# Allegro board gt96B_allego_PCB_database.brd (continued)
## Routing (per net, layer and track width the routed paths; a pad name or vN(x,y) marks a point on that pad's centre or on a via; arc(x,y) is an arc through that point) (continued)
SDCARD_CMD_CONN: length 19.1
  TOP w0.201: J5.3 8.34,1.75 9.04,2.45 v1(9.28,2.45)
  L3 w0.151: v1(10.15,16.83) 11.22,15.76 11.22,15.73 11.38,15.57 11.38,2.93 10.9,2.45 v1(9.28,2.45)
  L5 w0.084: v4(9.25,17.03) 9.95,17.03 v1(10.15,16.83)
SDCARD_D0: length 38.1
  L5 w0.084: v1(9.26,22.05) 9.9,22.05 10.45,21.49 15.39,21.49 18.68,18.2 33.52,18.2 35.75,20.43 37.65,20.43 38.88,21.66 v1(38.88,22.51)
  BOTTOM w0.201: v1(9.26,22.05) 9.2,22 9.2,21.41 9.25,21.36 U1.D1 ; J2.81 v1(38.88,22.51)
SDCARD_D0_CONN: length 19.6
  TOP w0.201: v1(4.24,2.45) 3.75,2.45 3.68,2.38 3.68,1.81 J5.7
  L3 w0.151: v1(9.37,15.79) 9.2,15.62 9.2,14.97 9.26,14.91 9.26,14.56 9.2,14.5 9.2,7.71 5.11,3.62 3.59,3.62 3.49,3.52 3.49,3.38 3.75,3.12 4.11,3.12 4.24,2.99 v1(4.24,2.45)
  BOTTOM w0.201: v1(9.37,15.79) 9.37,16.42 9.25,16.54 U1.D5
SDCARD_D1: length 37.5
  L5 w0.084: v1(39.28,22.06) 39.28,21.78 37.73,20.23 35.83,20.23 33.6,18 18.6,18 15.31,21.29 9.96,21.29 v1(9.65,21.6)
  BOTTOM w0.1: J2.83 v1(39.28,22.06)
  BOTTOM w0.201: U1.E1 v1(9.65,21.6)
SDCARD_D1_CONN: length 20.2
  TOP w0.201: J5.8 2.84,2.15 v1(2.54,2.45)
  L3 w0.151: v1(2.54,2.45) 2.97,2.02 4.51,2.02 4.75,2.26 4.75,2.73 9.51,7.49 9.51,15.17 v1(9.95,15.61)
  BOTTOM w0.201: U1.E5 9.82,16.46 9.82,15.72 9.96,15.58 9.96,15.61 v1(9.95,15.61)
SDCARD_D2: length 38.2
  L5 w0.084: v1(8.05,19.95) 9.13,19.95 10.27,21.09 15.22,21.09 18.51,17.8 33.68,17.8 35.91,20.03 37.82,20.03 39.68,21.89 v1(39.68,22.51)
  BOTTOM w0.201: J2.85 v1(39.68,22.51) ; v1(8.05,19.95) 8.05,19.74 8,19.69 8,19.31 8.05,19.26 U1.A1
SDCARD_D2_CONN: length 18.9
  TOP w0.201: v1(10.9,3.2) 10.54,2.84 J5.1
  L3 w0.151: v1(10.9,3.2) 11.09,3.39 11.09,15.5 10.96,15.63 10.96,15.65 10.26,16.35 9.86,16.35 9.62,16.59 8.11,16.59 7.9,16.38 7.9,16.12 v1(7.85,16.07)
  BOTTOM w0.201: U1.A5 7.85,16.43 v1(7.85,16.07)
SDCARD_D3: length 37.9
  L5 w0.084: v1(8.45,19.5) 9.04,19.5 10.43,20.89 15.14,20.89 18.43,17.6 33.77,17.6 36,19.83 37.92,19.83 40.08,21.99 v1(40.08,22.06)
  BOTTOM w0.1: J2.87 v1(40.08,22.06)
  BOTTOM w0.201: U1.B1 v1(8.45,19.5)
SDCARD_D3_CONN: length 20
  TOP w0.201: v1(7.81,3.2) 9.18,3.2 9.78,2.6 9.78,2.09 9.44,1.75 J5.2
  L3 w0.151: v1(8.45,16.16) 8.51,16.22 9.55,16.22 9.72,16.05 10.12,16.05 10.81,15.36 10.81,6.2 v1(7.81,3.2)
  BOTTOM w0.201: v1(8.45,16.16) 8.45,16.16 U1.B5
SDCARD_LVL_CLK_FB: length 37.3
  L5 w0.084: v1(38.08,22.51) 38.08,21.43 37.48,20.83 35.58,20.83 33.35,18.6 18.84,18.6 14.54,22.91 11.41,22.91 10.57,22.06 v1(10.45,22.06)
  BOTTOM w0.15: 9.77,17.9 9.94,18.07
  BOTTOM w0.201: 9.94,18.07 9.98,18.11 9.98,21.01 10.45,21.48 v1(10.45,22.06) ; J2.77 v1(38.08,22.51) ; U1.E2 9.73,17.9 9.77,17.9
SDCARD_LVL_CMD_DIR: length 45.3
  L5 w0.084: v1(40.58,25.25) 40.58,23.36 40.33,23.11 35.03,23.11 34.68,22.76 34.68,21.35 33.98,20.64 32.56,20.64 31.41,19.5 28.94,19.5 28.64,19.8 18.49,19.8 14.79,23.5 8.9,23.5 v1(7.81,22.41)
  BOTTOM w0.1: 7.54,18.28 7.45,18.38 7.45,18.62 7.5,18.67
  BOTTOM w0.201: 7.5,18.67 7.63,18.8 7.63,19.73 7.6,19.76 7.6,20.13 7.63,20.16 7.63,22.23 v1(7.81,22.41) ; v1(40.58,25.25) 40.48,25.35 J2.90 ; U1.A2 7.99,17.83 7.54,18.28
SDCARD_LVL_DAT_DIR: length 40.8
  L3 w0.151: v1(7.12,17.92) 7.16,17.96 10.53,17.96 v1(10.58,17.91)
  L5 w0.084: v1(10.55,22.89) 10.96,23.3 14.71,23.3 18.41,19.6 28.55,19.6 28.85,19.3 31.48,19.3 32.62,20.44 34.63,20.44 36.08,21.89 v1(36.08,22.51)
  BOTTOM w0.1: 7.97,17.43 7.96,17.43 7.64,17.75 ; J2.67 v1(36.08,22.51) ; U1.E3 10.05,17.83 10.13,17.83 10.18,17.88
  BOTTOM w0.201: v1(7.12,17.92) 7.29,17.75 7.64,17.75 ; 10.18,17.88 10.55,17.88 v1(10.58,17.91) 10.9,18.23 10.9,18.77 10.9,18.77 10.9,19.32 10.9,19.33 10.9,19.53 10.9,19.54 10.9,20.09 10.9,20.09 10.9,20.17 10.9,20.17 10.9,20.54 10.9,20.54 10.9,22.54 v1(10.55,22.89) ; 7.97,17.43 U1.A3
SDCARD_LVL_SEL: length 45.7
  L5 w0.084: v1(7.32,22.97) 7.36,22.93 7.48,22.93 8.26,23.7 14.87,23.7 18.58,20 28.72,20 29.02,19.7 31.35,19.7 32.5,20.84 33.89,20.84 34.48,21.43 34.48,22.84 34.95,23.31 39.83,23.31 40.14,23.62 v1(40.14,24.85) ; v1(7.16,19.25) 8.45,17.96 v4(8.45,17.88)
  BOTTOM w0.1: U1.B2 v4(8.45,17.88)
  BOTTOM w0.201: v1(7.32,22.97) 7.27,22.93 7.27,20.85 7.16,20.74 v1(7.16,19.25) ; J2.88 40.08,24.91 v1(40.14,24.85)
SDCARD_PWR_DOWN_N: length 38.9
  L5 w0.084: v1(40.88,21.78) 40.76,21.66 40.03,21.66 37.99,19.62 36.07,19.62 33.85,17.4 18.35,17.4 15.06,20.69 10.78,20.69 v1(10.45,20.36) 8.85,18.76 v4(8.85,17.83)
  BOTTOM w0.1: J2.91 v1(40.88,21.78)
  BOTTOM w0.201: v1(10.45,20.36) 10.45,20.35 R36.1
SPI_0_CLK: length 32.8
  TOP w0.1: v3(18.98,40.88) 18.76,40.66 18.76,39.19 19.2,38.75 19.2,34.97 20.71,33.46 20.71,23.53 21.17,23.07 21.17,22.19 21.39,21.97 21.39,20.08 20.55,19.24 20.55,16.5 22.43,14.62 23.21,14.62 23.43,14.4 23.95,14.4 24.35,14 J13.9
  BOTTOM w0.1: J3.59 v3(18.98,40.88)
SPI_0_FS0: length 36.3
  TOP w0.1: v1(22.57,38.44) 22.58,38.45 v1(22.58,41.42) ; J13.7 23.55,13.99 23.12,14.42 22.35,14.42 20.35,16.42 20.35,19.33 21.19,20.17 21.19,21.89 20.97,22.11 20.97,22.97 20.35,23.59 20.35,33.39 18.98,34.76 18.98,38.17 v3(18.73,38.42)
  BOTTOM w0.1: v3(18.73,38.42) 19.18,37.97 22.1,37.97 v1(22.57,38.44) ; J3.77 v1(22.58,41.42)
SPI_0_MISO: length 36.1
  TOP w0.1: v1(19.16,40.17) 18.96,39.97 18.96,39.27 19.4,38.84 19.4,38.55 19.9,38.05 v2(20.32,38.05) 19.55,37.28 19.55,35.08 20.98,33.65 20.98,23.69 21.37,23.3 21.37,22.27 21.59,22.05 21.59,20 20.75,19.16 20.75,16.59 22.52,14.82 23.29,14.82 23.51,14.6 24.55,14.6 25.15,14 J13.11
  BOTTOM w0.1: v1(19.16,40.17) 18.96,39.97 18.07,39.97 16.98,41.06 J3.49
SPI_0_MOSI: length 31
  TOP w0.1: J13.1 21.15,15.34 20.15,16.34 20.15,18.92 18.28,20.79 18.28,29.91 18.98,30.62 18.98,31.04 18.99,31.05 18.99,31.65 18.98,31.66 18.98,33.93 v2(18.53,34.38) 18.62,34.47 18.62,37.55 18.23,37.94 18.23,40.27 18.36,40.4 v1(18.36,40.52)
  BOTTOM w0.1: v1(18.36,40.52) 18.36,40.57 18.44,40.65 18.44,40.99 18.58,41.13 J3.57
SPI_1_CLK: length 47.5
  TOP w0.1: v1(15.01,52.76) 15.01,52.76 15.66,52.76 16,52.42 J12.8 ; v1(33.38,21.9) 33.83,22.35 33.83,23.23 34.59,23.99 34.77,23.99 34.88,24.09 34.88,26.17 33.48,27.56 33.2,27.56 32.73,28.03 32.73,28.32 32.14,28.9 31.48,29.56 31.48,29.62 31.28,29.82 31.28,30.08 30.26,31.1 30.26,32.43 30.07,32.62 30.07,38.06 30.08,38.07 30.08,41.52 29.8,41.8 v1(29.8,41.96)
  BOTTOM w0.1: v1(29.8,41.96) 29.72,42.04 29.39,42.04 28.8,42.63 28.8,45.25 27.21,46.84 25.45,46.84 24.92,47.38 24.25,47.38 22.18,49.44 22.18,51.09 21.43,51.84 16.58,51.84 15.66,52.76 v1(15.01,52.76) ; v1(33.38,21.9) 33.38,22.66 33.28,22.76 J2.53
SPI_1_FS0: length 45.1
  TOP w0.1: v1(30.2,42.77) 30.2,41.68 30.28,41.6 30.28,37.99 30.27,37.98 30.27,32.7 30.46,32.52 30.46,31.19 31.48,30.16 31.48,29.91 31.68,29.71 31.68,29.65 32.23,29.1 32.93,28.4 32.93,28.11 33.28,27.76 33.57,27.76 35.08,26.25 35.08,23.91 34.2,23.03 34.2,21.82 v1(33.78,21.4) ; v1(19.09,52.76) 19.46,52.76 J12.12
  BOTTOM w0.1: v1(30.2,42.77) 30.2,42.74 30.02,42.56 29.43,42.56 29.2,42.79 29.2,45.42 27.38,47.24 25.62,47.24 25.08,47.78 24.42,47.78 22.59,49.61 22.59,51.37 21.71,52.24 19.99,52.24 19.47,52.76 v1(19.09,52.76) ; v1(33.78,21.4) 33.78,22.64 33.68,22.74 J2.55
SPI_1_MISO: length 44.8
  TOP w0.1: J12.10 17.48,52.74 v1(17.09,52.74) ; v1(30.81,42.55) 30.47,42.21 30.47,41.7 30.48,41.69 30.48,37.91 30.47,37.9 30.47,32.79 30.66,32.6 30.66,31.27 31.68,30.25 31.68,29.99 31.88,29.79 31.88,29.73 32.31,29.3 33.13,28.48 33.13,28.2 33.36,27.96 33.65,27.96 35.28,26.33 v1(35.28,22.51)
  BOTTOM w0.1: v1(17.09,52.74) 17.49,52.74 18.19,52.04 21.63,52.04 22.39,51.28 22.39,49.53 24.34,47.58 25,47.58 25.53,47.04 27.3,47.04 29,45.34 29,42.71 29.35,42.36 30.62,42.36 v1(30.81,42.55) ; J2.63 v1(35.28,22.51)
SPI_1_MOSI: length 43.2
  TOP w0.1: v1(21.09,52.71) 21.51,52.71 J12.14 ; v1(29.6,42.96) 29.4,42.76 29.4,41.57 29.48,41.49 29.48,40.76 29.88,40.36 29.88,38.16 29.87,38.15 29.87,32.54 30.06,32.35 30.06,31.02 31.08,30 31.08,29.74 31.28,29.54 31.28,29.48 32.06,28.7 32.53,28.23 32.53,27.95 33.12,27.36 33.4,27.36 33.89,26.88 33.89,25.21 32.88,24.21 32.88,22.6 v1(32.97,22.5)
  BOTTOM w0.1: v1(32.97,22.5) 32.88,22.6 J2.51 ; v1(21.09,52.71) 21.52,52.71 22.79,51.45 22.79,49.69 23.19,49.29 24.16,49.29 25.52,50.66 25.52,50.89 25.61,50.97 27.01,50.97 27.09,50.89 27.09,47.81 29.4,45.5 29.4,43.06 29.5,42.96 v1(29.6,42.96)
TP_HDMI_CEC: length 9.1
  TOP w0.1: J10.13 23.75,8.23 22.23,6.71 17.2,6.71 TP1.1
TP_USB_TYPC_SBU1_CONN: length 1.8
  TOP w0.1: J7.A8 42.45,10.24 42.45,11.68 TP17.1
TP_USB_TYPC_SBU2_CONN: length 10.2
  TOP w0.1: J7.B8 41.4,7.63 41.4,5.67 39.03,3.3 TP18.1
UART_0_CTS: length 9.2
  TOP w0.1: v3(16.58,41.5) 15.38,42.7 15.38,43.67 14.74,44.31 14.74,45.64 14,46.38 13.95,46.38 13.82,46.51 13.44,46.51 13.17,46.78 13,46.78 J12.3
  BOTTOM w0.1: J3.47 v3(16.58,41.5)
UART_0_RTS: length 8.1
  TOP w0.1: v1(18.18,41.31) 18.18,42.81 17.16,43.83 17.16,43.97 17.18,43.99 17.18,44.23 18,45.05 J12.9
  BOTTOM w0.1: J3.55 v1(18.18,41.31)
UART_0_RXD: length 10.2
  TOP w0.1: v1(17.8,40.8) 17.8,41.12 17.78,41.14 17.78,41.47 17.98,41.67 17.98,42.73 16.96,43.75 16.96,44.05 16.98,44.07 16.98,44.31 17.78,45.11 17.78,46.16 16.16,47.78 J12.7
  BOTTOM w0.1: J3.51 17.38,41.22 v1(17.8,40.8)
UART_0_TXD: length 48.2
  TOP w0.1: J12.5 14,47.31 14.97,46.34 15.11,46.34 v1(15.15,46.38) ; v3(31.03,41.76) 30.68,41.41 30.68,37.82 30.67,37.82 30.67,32.87 30.86,32.68 30.86,31.35 32.09,30.12 33.89,30.12 38.08,25.93 38.08,24.91 39.27,23.72 40.07,23.72 v1(41.28,22.51)
  BOTTOM w0.1: v1(41.28,22.51) J2.93 ; v1(15.15,46.38) 15.95,47.17 24.83,47.17 25.37,46.64 27.13,46.64 28.6,45.17 28.6,42.55 29.61,41.54 30.81,41.54 v3(31.03,41.76)
UART_1_RXD: length 1.5
  TOP w0.1: TP8.1 27.16,26.47 v1(27.68,26.99)
  BOTTOM w0.1: J2.26 v1(27.68,26.99)
UART_1_TXD: length 2.7
  TOP w0.1: TP9.1 28.08,26.74 v3(28.08,27.66)
  BOTTOM w0.1: v3(28.08,27.66) J2.28
UART_2_CTS: length 30.3
  TOP w0.1: v3(36.88,29.41) 37.15,29.68 37.78,29.68 38.67,30.57 38.67,35.3 37.51,36.46 37.51,40.15 36.82,40.84 36.82,41.08 35.69,42.21 35.69,45.13 34.84,45.98 33.83,45.98 33.11,46.7 33.11,49.06 33.05,49.12 v1(33.05,49.59)
  BOTTOM w0.1: J9.6 33.93,50.98 33.05,50.1 v1(33.05,49.59) ; J2.74 37.28,29.01 v3(36.88,29.41)
UART_2_RTS: length 40
  TOP w0.1: v1(37.75,28.45) 37.75,29.27 37.97,29.49 37.97,29.58 38.87,30.48 38.87,35.39 38.31,35.95 38.31,37.42 38.1,37.63 38.1,38.29 37.91,38.48 37.91,40.31 37.22,41 37.22,41.24 36.09,42.37 36.09,45.29 34.71,46.67 34.71,48.98 v1(34.51,49.18)
  BOTTOM w0.1: J2.76 37.68,27.99 37.75,28.06 v1(37.75,28.45) ; J9.2 24.23,51.57 27.26,51.57 27.7,51.13 27.7,50.29 28.42,49.57 29.25,49.57 30.23,50.55 30.23,50.78 30.42,50.97 32.09,50.97 32.27,50.79 32.27,49.25 32.53,48.99 34.32,48.99 v1(34.51,49.18)
UART_2_RXD: length 44.3
  TOP w0.1: v1(35.58,49.18) 35.28,48.88 35.28,46.67 36.49,45.46 36.49,42.54 38.31,40.72 38.31,38.65 38.5,38.46 38.5,37.79 38.71,37.58 38.71,36.12 39.27,35.56 39.27,30.32 38.95,30 v1(38.95,28.38) ; J12.13 22,48.23 23.03,49.26 28.14,49.26 v1(28.85,49.97)
  BOTTOM w0.1: J9.4 v1(28.85,49.97) 29.37,49.97 30.03,50.63 30.03,50.86 30.34,51.17 30.51,51.17 32.17,51.17 32.55,50.79 32.55,49.52 32.88,49.19 33.95,49.19 34.34,49.58 34.68,49.58 35.08,49.18 v1(35.58,49.18) ; v1(38.95,28.38) 38.95,28.32 38.48,27.85 J2.80
UART_2_TXD: length 80.7
  TOP w0.1: v1(38.39,28.99) 38.39,29.72 39.07,30.4 39.07,35.47 38.51,36.03 38.51,37.5 38.3,37.71 38.3,38.38 38.11,38.57 38.11,40.39 37.42,41.08 37.42,41.33 36.29,42.46 36.29,45.38 34.91,46.76 34.91,49.28 35.48,49.85 v1(35.48,49.89) ; J12.11 20,48.27 21.67,49.94 v1(23.39,49.94) ; SW3.2 SW3.1 ; SW3.2 56.99,51.17 CR23.1 ; SW3.2 57.22,49.96 57.55,49.63 57.55,49.57 57.45,49.47 v1(57.39,49.47)
  TOP w0.2: CR23.1 v2(56.15,52.85)
  L3 w0.1: v1(57.39,49.47) 57.39,49.41 56.36,48.38 36.94,48.38 35.48,49.84 v1(35.48,49.89)
  BOTTOM w0.1: v1(35.48,49.89) 35.54,49.84 35.58,49.84 36.05,49.37 36.05,48.99 35.77,48.71 32.52,48.71 32.13,49.11 J9.5 28.59,49.11 27.5,50.2 27.5,51.05 27.17,51.37 25.45,51.37 25.12,51.05 25.12,50.82 24.24,49.94 v1(23.39,49.94) ; J2.78 38.08,27.73 38.39,28.04 v1(38.39,28.99)
UNNAMED_11_RES_I102_B: length 0.6
  TOP w0.1: U2.60 58.45,33.69 R64.2
UNNAMED_20_FPF2195_I476_ON: length 0.9
  TOP w0.1: U24.A2 44.4,44.11 R138.2
UNNAMED_56_CAP_I271_B: length 1.9
  BOTTOM w0.2: R23.1 58.08,46.88 58.45,47.25 v2(58.45,47.26)
  BOTTOM w0.3: R23.1 58.08,45.55
UNNAMED_56_CAP_I302_B: length 2.2
  BOTTOM w0.2: R80.1 62.56,20.57 62.96,20.97 v2(62.96,21.04)
  BOTTOM w0.35: C150.2 R80.1
USB2_0_DN: length 29.8
  L3 w0.117: v1(42.55,16.19) 42.58,16.19 42.58,16.17 42.31,16.17 42.29,16.19 41.88,16.19 39.84,18.22 39.64,18.22 31.51,18.22 29.65,20.08 29.65,20.3 26.68,23.27 25.72,23.27 23.95,25.04 23.95,27.05 24.1,27.21 v1(24.1,27.46)
  BOTTOM w0.112: v1(42.55,16.19) 42.58,16.19 42.58,16.15 42.53,16.1 42.53,15.61 42.4,15.48 42.4,14.43 42.6,14.23 42.6,12.84 U4.B1 ; v1(24.1,27.46) 24.02,27.37 24.02,26.78 24.08,26.71 J2.8
USB2_0_DP: length 29.9
  L3 w0.117: v1(42.12,15.78) 42.12,15.77 41.94,15.59 41.78,15.59 41.66,15.71 41.66,16.05 39.74,17.97 31.41,17.97 29.4,19.98 29.4,20.2 26.58,23.02 25.62,23.02 23.7,24.94 23.7,27.35 v1(23.51,27.55)
  BOTTOM w0.112: J2.6 23.68,26.71 23.74,26.78 23.74,27.24 23.7,27.29 23.7,27.36 v1(23.51,27.55) ; v1(42.12,15.78) 42.12,15.78 42.12,15.78 42.14,15.77 42.14,15.61 42.12,15.59 42.12,14.32 42.32,14.12 42.32,12.84 U4.A1
USB2_1_DN: length 48.9
  TOP w0.112: v1(61.25,32.48) 61.45,32.68 U2.54
  L3 w0.117: v1(61.25,32.48) 61.25,32.77 61.13,32.89 59.83,32.89 59.65,32.71 58.57,32.71 56.74,34.54 52.45,34.54 52.13,34.86 51.36,34.86 51.02,34.52 24.36,34.52 20.53,38.35 20.53,39.98 20.11,40.39 v1(19.76,40.39)
  BOTTOM w0.112: J3.63 19.78,41.78 19.84,41.71 19.84,40.48 v1(19.76,40.39)
USB2_1_DP: length 48.8
  TOP w0.112: U2.53 61.95,32.58 v1(61.85,32.48)
  L3 w0.117: v1(61.85,32.48) 61.85,32.75 61.72,32.88 61.5,32.88 61.24,33.14 59.72,33.14 59.55,32.96 58.68,32.96 56.85,34.79 52.55,34.79 52.23,35.11 51.26,35.11 50.92,34.77 24.46,34.77 20.78,38.45 20.78,40.08 20.29,40.57 v1(20.29,40.93)
  BOTTOM w0.112: v1(20.29,40.93) 20.12,41.1 20.12,41.71 20.18,41.78 J3.65
USB2_ID_PMIC: length 2.1
  TOP w0.1: TP14.1 26.48,27.29 v1(26.41,27.36)
  BOTTOM w0.1: J2.20 26.48,27.29 v1(26.41,27.36)
USB3_0_MUX1_RX_DN: length 25.7
  TOP w0.112: v1(14.42,14.99) U6.16 ; v1(34.47,6.43) 34.56,6.53 L7.3
  L3 w0.117: v1(14.42,14.99) 14.42,14.86 14.68,14.6 14.68,14.22 20.05,8.85 29.66,8.85 30.43,8.08 30.43,7.54 31.39,6.58 34.32,6.58 v1(34.47,6.43)
USB3_0_MUX1_RX_DP: length 25.6
  TOP w0.112: v1(14.92,15.33) U6.17 ; L7.4 v1(34.47,7.04)
  L3 w0.117: v1(34.47,7.04) 34.47,6.95 34.35,6.83 34.09,6.83 33.82,7.1 33.65,7.1 33.38,6.83 33.2,6.83 33.01,7.02 32.85,7.02 32.66,6.83 31.49,6.83 30.68,7.64 30.68,8.18 29.76,9.1 20.15,9.1 14.93,14.32 14.93,15.32 v1(14.92,15.33)
USB3_0_MUX1_TX_DN: length 25.9
  TOP w0.112: U6.18 v1(15.42,14.99)
  L3 w0.117: v1(36.38,10.67) 36.33,10.72 36.16,10.72 35.87,10.43 34.24,10.43 33.78,9.97 33.16,9.97 32.65,10.48 31.23,10.48 30.59,9.84 20.53,9.84 16.38,13.99 16.38,14.19 15.58,14.99 v1(15.42,14.99)
  BOTTOM w0.112: v1(36.38,10.67) 36.38,10.67 36.38,10.67 36.28,10.77 36.28,11.58
USB3_0_MUX1_TX_DP: length 25.9
  TOP w0.112: U6.19 v1(15.92,15.33)
  L3 w0.117: v1(15.92,15.33) 15.82,15.23 15.83,15.23 15.83,15.1 16.63,14.29 16.63,14.09 20.63,10.09 30.49,10.09 31.13,10.73 32.75,10.73 33.26,10.22 33.68,10.22 34.14,10.68 34.76,10.68 34.88,10.8 34.88,10.99 34.96,11.07 35.16,11.07 35.28,10.95 35.28,10.8 35.39,10.68 35.77,10.68 36.06,10.97 36.1,10.97 36.21,11.08 36.54,11.08 36.56,11.1 v1(36.8,11.1)
  BOTTOM w0.112: v1(36.8,11.1) L6.4
USB3_0_MUX2_RX_DN: length 57.4
  TOP w0.112: v1(48.34,9.19) 48.3,9.23 48.3,9.68 ; v1(12.42,15) 12.42,15.01 U6.12
  L3 w0.117: v1(12.42,15) 12.45,14.97 12.45,13.96 12.74,13.67 12.74,13.03 12.58,12.87 12.58,12.67 12.58,12.66 12.58,10.19 13.12,9.65 13.12,2.58 14.77,0.92 46.51,0.92 48.33,2.74 48.33,9.18 v1(48.34,9.19)
USB3_0_MUX2_RX_DP: length 57.3
  TOP w0.112: U6.13 v1(12.92,15.34) ; L9.4 47.78,9.26 v1(47.73,9.2)
  L3 w0.117: v1(12.92,15.34) 12.92,14.89 12.7,14.67 12.7,14.06 12.99,13.77 12.99,12.93 12.83,12.77 12.83,10.29 13.37,9.75 13.37,2.68 14.88,1.17 46.41,1.17 48.08,2.84 48.08,7.28 47.52,7.84 47.52,8.08 48.08,8.64 48.08,8.87 47.75,9.2 v1(47.73,9.2)
USB3_0_MUX2_TX_DN: length 44.9
  TOP w0.112: U6.14 v1(13.42,15)
  L3 w0.117: v1(13.42,15) 13.58,14.84 13.58,13.83 14.68,12.73 14.68,7.77 16.43,6.02 17.97,6.02 20.46,3.53 30.23,3.53 32.1,5.4 34,5.4 36.67,2.73 41.84,2.73 44.2,5.09 44.2,5.7 43.96,5.94 43.35,5.94 v1(43.35,5.94)
  BOTTOM w0.112: v1(43.35,5.94) 43.34,5.94 L8.3
USB3_0_MUX2_TX_DP: length 44.8
  TOP w0.112: U6.15 v1(13.92,15.34)
  L3 w0.117: v1(13.92,15.34) 13.83,15.24 13.83,13.93 14.93,12.83 14.93,7.87 16.53,6.27 18.07,6.27 20.56,3.78 30.13,3.78 32,5.65 34.1,5.65 36.77,2.98 41.74,2.98 42.13,3.37 42.13,3.53 41.71,3.95 41.71,4.11 41.88,4.28 42.05,4.28 42.46,3.87 42.63,3.87 43.95,5.19 43.95,5.37 v1(43.79,5.53)
  BOTTOM w0.112: v1(43.79,5.53) 43.75,5.57 43.75,6.31 L8.4
USB3_0_RX_DN: length 35.9
  TOP w0.112: U6.8 v1(12.92,19.02)
  L3 w0.117: v1(12.92,19.02) 13.18,19.28 13.18,23.27 9.26,27.19 9.26,41.73 10.76,43.23 10.76,44.15 11.51,44.9 15.82,44.9 16.09,45.17 16.09,45.84 15.95,45.98 v1(15.76,45.98)
  BOTTOM w0.112: v1(15.76,45.98) 15.78,45.96 J3.44
USB3_0_RX_DP: length 36
  TOP w0.112: v1(13.42,18.68) U6.7
  L3 w0.117: v1(16.34,46.17) 16.34,45.06 15.92,44.65 11.61,44.65 11.01,44.05 11.01,43.13 9.51,41.63 9.51,27.29 13.43,23.37 13.43,18.77 13.42,18.76 v1(13.42,18.68)
  BOTTOM w0.112: v1(16.34,46.17) 16.18,46.02 J3.46
USB3_0_TX_DN: length 38
  TOP w0.112: U6.4 v1(14.92,18.68)
  L3 w0.117: v1(8.18,46.19) 8.18,46.06 8.02,45.9 8.02,45.55 7.63,45.16 6.9,45.16 6.22,44.48 6.22,43.96 6.34,43.85 6.77,43.85 6.89,43.73 6.89,43.49 6.77,43.38 6.34,43.38 6.22,43.26 6.22,28.6 12.24,22.58 12.24,22.34 12.37,22.22 12.37,21.06 12.2,20.89 12.2,18.54 12.96,17.78 14.7,17.78 15.1,18.18 15.1,18.44 14.92,18.62 v1(14.92,18.68)
  BOTTOM w0.112: J3.6 v1(8.18,46.19)
USB3_0_TX_DP: length 38
  TOP w0.112: v1(15.42,19.02) U6.3
  L3 w0.117: v1(15.42,19.02) 15.41,19.01 15.41,18.63 15.35,18.56 15.35,18.07 14.8,17.53 12.86,17.53 11.95,18.43 11.95,20.99 12.12,21.16 12.12,22.11 11.99,22.24 11.99,22.48 5.97,28.5 5.97,44.58 6.82,45.43 7.54,45.43 7.77,45.66 7.77,45.82 v1(7.62,45.97)
  BOTTOM w0.112: v1(7.62,45.97) 7.78,45.81 J3.4
USB3_1_RX_DN: length 42.5
  TOP w0.112: v1(60.4,34.74) 60.49,34.65 C155.1
  L3 w0.117: v1(26.79,40.66) 26.79,40.61 26.91,40.5 27.84,40.5 28.22,40.88 36.63,40.88 38.53,38.98 45.67,38.98 46.67,37.98 48.14,37.98 49.26,39.1 51.82,39.1 52.35,39.63 56.28,39.63 57.17,38.75 57.33,38.75 57.81,39.23 57.97,39.23 58.14,39.06 58.14,38.89 57.66,38.42 57.66,38.25 58.28,37.63 58.28,36.33 59.1,35.52 59.62,35.52 v1(60.4,34.74)
  BOTTOM w0.112: J3.97 26.58,41.78 26.52,41.71 26.52,40.93 v1(26.79,40.66)
USB3_1_RX_DN_C: length 0.6
  TOP w0.112: C155.2 60.49,33.37 60.45,33.33 U2.56
USB3_1_RX_DP: length 42.4
  TOP w0.112: C154.1 60.98,34.16 v1(60.98,34.56)
  L3 w0.117: v1(26.03,40.66) 26.21,40.66 26.62,40.25 27.94,40.25 28.32,40.63 36.53,40.63 38.43,38.73 45.57,38.73 46.57,37.73 48.24,37.73 49.36,38.85 51.92,38.85 52.45,39.38 56.18,39.38 58.03,37.53 58.03,36.23 58.99,35.27 59.52,35.27 60,34.79 60,34.57 60.23,34.33 60.75,34.33 v1(60.98,34.56)
  BOTTOM w0.112: J3.95 26.18,41.78 26.24,41.71 26.24,40.87 v1(26.03,40.66)
USB3_1_RX_DP_C: length 0.6
  TOP w0.112: U2.55 60.95,33.58 61,33.63 C154.2
USB3_1_TX_DN: length 43.9
  TOP w0.112: U2.59 58.95,33.3 58.89,33.36 58.89,34.1 v1(59.05,34.25)
  L3 w0.117: v1(59.05,34.25) 58.9,34.11 58.78,34.11 57.57,35.32 57.57,35.81 56.25,37.12 56.25,37.28 55.86,37.68 54.14,37.68 53.29,36.83 51.08,36.83 50.51,36.27 49.74,36.27 49.43,35.96 37.29,35.96 34.64,38.61 28.37,38.61 27.67,37.91 25.23,37.91 24.92,38.22 24.92,40.88 24.98,40.94 v1(25.16,40.94)
  BOTTOM w0.112: J3.89 24.98,41.78 24.92,41.71 24.92,41.44 24.92,41.44 24.92,41.18 v1(25.16,40.94)
USB3_1_TX_DP: length 44
  TOP w0.112: U2.58 59.45,33.5 v1(59.3,33.65)
  L3 w0.117: v1(59.3,33.65) 59.11,33.84 58.69,33.84 57.32,35.22 57.32,35.7 56,37.02 56,37.18 55.75,37.43 54.24,37.43 53.39,36.58 51.18,36.58 50.62,36.02 49.84,36.02 49.53,35.71 37.19,35.71 34.54,38.36 28.47,38.36 27.77,37.66 25.13,37.66 24.67,38.12 24.67,40.88 24.61,40.94 v1(24.4,40.94)
  BOTTOM w0.112: J3.87 24.58,41.78 24.64,41.71 24.64,41.33 24.64,41.32 24.64,41.18 v1(24.4,40.94)
USB_HUB_AUTOEN_N: length 0.6
  TOP w0.1: U2.45 65.18,30.98
USB_HUB_OVERCUR1_N: length 21.5
  TOP w0.1: R2.2 66.83,31.48 U2.46 v1(63.61,31.48) ; v1(73.62,23.19) 73.59,23.19 U15.3
  L3 w0.1: v1(73.62,23.19) 73.62,24.45 74.45,25.28 74.45,26.33 73.59,27.18 67.15,27.18 66.09,28.24 66.09,29 v1(63.61,31.48)
USB_HUB_OVERCUR2_N: length 21.5
  TOP w0.1: v1(52.54,29.01) 52.38,29.17 U16.3 ; v1(63.95,31.98) U2.47 64.81,31.98 64.93,31.86 67.26,31.86 R3.2
  L3 w0.1: v1(52.54,29.01) 52.13,29.42 52.13,32.5 52.91,33.28 55.33,33.28 55.53,33.08 57.2,33.08 59.48,30.8 62.36,30.8 63.54,31.98 v1(63.95,31.98)
USB_HUB_OVERCUR3_N: length 3.3
  TOP w0.1: U2.44 67.17,30.48 67.4,30.25 TP11.1
USB_HUB_OVERCUR4_N: length 3.6
  TOP w0.1: U2.43 64.65,29.98 64.95,30.28 67.09,30.28 67.73,29.64 TP12.1
USB_HUB_PWRCTL1: length 13.9
  TOP w0.1: v1(63.95,26.48) U2.36 64.9,26.48 65.09,26.29 R38.2 ; R104.1 73.91,25.38 73.91,25.45 v1(73.67,25.69) 73.59,25.61 U15.4
  L3 w0.1: v1(73.67,25.69) 73.58,25.78 68.78,25.78 68.61,25.95 67.84,25.95 67.31,26.48 v1(63.95,26.48)
USB_HUB_PWRCTL2: length 20.2
  TOP w0.1: v1(63.61,25.98) U2.35 66.04,25.98 66.54,25.49 R28.2 ; v1(52.88,31.37) 52.62,31.37 U16.4 R103.1
  L3 w0.1: v1(63.61,25.98) 63.55,26.04 63.55,26.45 57.12,32.88 55.45,32.88 55.25,33.08 52.99,33.08 52.57,32.65 52.57,31.92 52.88,31.61 v1(52.88,31.37)
USB_HUB_PWRCTL3: length 1.3
  TOP w0.1: TP13.1 64.31,24.75 U2.33
USB_HUB_PWRCTL4: length 1.3
  TOP w0.1: TP15.1 63.95,23.35 U2.32
USB_HUB_RST: length 52
  TOP w0.1: Q1.1 v1(66.31,35.41)
  L3 w0.1: v3(21.78,41.42) 21.78,41.84 23.76,43.82 28.54,43.82 30.38,45.66 35.92,45.66 36.04,45.54 38.87,45.54 42.33,42.08 56.82,42.08 60.2,38.7 61.68,38.7 64.94,35.44 66.29,35.44 v1(66.31,35.41)
  BOTTOM w0.1: J3.73 v3(21.78,41.42)
USB_HUB_SCL: length 0.8
  TOP w0.1: U2.38 65.02,27.48 TP16.1
USB_HUB_SDA: length 1.9
  TOP w0.1: TP19.1 65.61,26.74 65.01,26.74 64.77,26.98 U2.37
USB_HUB_SMBUS_N: length 2.5
  TOP w0.1: U2.39 TP20.1 65.55,27.98 65.78,27.75 66.39,27.75 66.79,27.36
USB_HUB_TEST: length 1.6
  TOP w0.1: U2.49 64.29,33.07 65.18,33.95
USB_R1: length 1.7
  TOP w0.1: R43.2 56.45,33.07 U2.64
USB_TYPC_CC1: length 13.8
  BOTTOM w0.2: J2.59 34.48,22.76 34.45,22.73
  BOTTOM w0.25: v2(35.19,20.47) 35.19,21.11 34.45,21.84 34.45,22.73
  BOTTOM w0.3: v2(35.19,20.47) 35.67,19.99 35.79,19.99 36.06,19.72 36.13,19.72 36.16,19.69 38.63,19.69 38.93,19.99 39.4,19.99 39.74,19.65 39.74,19.17 40.1,18.8 40.1,17 40.8,16.3 40.8,15.53 40.81,15.53 40.81,15.49 40.85,15.44 C20.1 40.85,15.21 FB4.2
USB_TYPC_CC2: length 33.8
  BOTTOM w0.2: J2.61 34.88,22.79
  BOTTOM w0.25: 34.83,22 34.8,22.02 34.8,22.71 34.88,22.78 34.88,22.79
  BOTTOM w0.3: FB5.2 41.32,6.36 C19.1 v2(41.32,4.69) 40.97,4.69 40.47,5.19 40.47,5.64 40.03,6.08 38.48,6.08 37.77,6.79 36.55,6.79 35.87,7.47 35.87,9.12 37.51,10.76 38.44,10.76 38.76,10.44 39.55,10.44 39.95,10.84 40.3,10.84 40.85,11.39 41.16,11.39 41.45,11.69 41.45,12.18 41.35,12.27 41.35,16.28 41.2,16.43 41.2,16.46 40.5,17.17 40.5,18.97 40.14,19.33 40.14,19.82 39.57,20.39 38.77,20.39 38.47,20.09 36.33,20.09 36.3,20.12 36.23,20.12 35.96,20.38 35.96,20.39 35.96,20.39 35.86,20.48 35.86,20.67 35.56,20.96 35.56,21.26 34.83,22
USB_TYPC_CONN_CC1: length 5
  TOP w0.2: J7.A5 40.85,11.85 40.89,11.89 v1(40.95,11.89)
  BOTTOM w0.2: v2(39.66,13.58) 39.81,13.74 FB4.1
  BOTTOM w0.25: v1(40.95,11.89) 40.85,11.99 CR12.1 40.85,13.73 FB4.1
USB_TYPC_CONN_CC2: length 2.9
  BOTTOM w0.25: FB5.1 41.32,7.14 CR11.1 42.01,7.84 J7.B5
  BOTTOM w0.3: FB5.1 40.54,7.13 40.46,7.21 v2(40.37,7.21)
USB_VBUS: length 2.8
  TOP w0.2: v2(66.84,33.43) 66.25,32.83 66.14,32.83 66.08,32.78 66.08,32.57 R30.2
  TOP w0.25: U2.48 64.54,32.48 64.95,32.48
  TOP w0.35: R30.2 65.28,32.48 R35.1 64.95,32.48
USBA_1_USB2_1_DN: length 4.5
  TOP w0.112: U20.A1 74.87,14.76 74.93,14.69 74.93,14.33 74.97,14.28 74.97,12.77 75.86,11.88 75.86,11.74 75.75,11.63 J6.2
USBA_1_USB2_1_DP: length 4.5
  TOP w0.112: U20.B1 75.27,14.76 75.21,14.69 75.21,14.44 75.25,14.4 75.25,12.88 76.14,12 76.14,11.74 76.25,11.63 J6.3
USBA_1_USB3_1_RX_DN: length 3.2
  TOP w0.112: L3.1 78.19,14.68 78.08,14.57 78.08,14.42 78.36,14.42 79.14,13.64 79.14,13.24 79.25,13.13 J6.5
USBA_1_USB3_1_RX_DP: length 3.2
  TOP w0.112: L3.2 77.69,14.68 77.8,14.57 77.8,14.31 77.96,14.15 78.24,14.15 78.86,13.53 78.86,13.24 78.75,13.13 J6.6
USBA_1_USB3_1_TX_DN: length 2.6
  TOP w0.112: L4.1 73.25,14.68 73.14,14.57 73.14,13.24 73.25,13.13 J6.8
USBA_1_USB3_1_TX_DP: length 2.6
  TOP w0.112: J6.9 72.75,13.13 72.86,13.24 72.86,14.57 72.75,14.68 L4.2
USBA_2_USB2_1_DN: length 4.5
  TOP w0.112: J8.2 56.35,11.63 56.46,11.74 56.46,11.88 55.48,12.87 55.48,14.86 U19.A1
USBA_2_USB2_1_DP: length 4.5
  TOP w0.112: J8.3 56.85,11.63 56.74,11.74 56.74,12 55.76,12.98 55.76,14.89 U19.B1
USBA_2_USB3_1_RX_DN: length 2.6
  TOP w0.112: J8.5 59.85,13.13 59.74,13.24 59.74,14.57 59.85,14.68 L14.1
USBA_2_USB3_1_RX_DP: length 2.6
  TOP w0.112: J8.6 59.35,13.13 59.46,13.24 59.46,14.57 59.34,14.68 L14.2
USBA_2_USB3_1_TX_DN: length 2.6
  TOP w0.112: J8.8 53.85,13.13 53.74,13.24 53.74,14.57 53.85,14.68 L15.1
USBA_2_USB3_1_TX_DP: length 2.6
  TOP w0.112: J8.9 53.35,13.13 53.46,13.24 53.46,14.57 53.34,14.68 L15.2
USBA_CONN1_I_ADJ: length 2.1
  TOP w0.2: U15.2 72.52,22.92 72.72,22.72 72.85,22.72 ; 72.85,22.72 v2(72.85,22.69) ; 72.85,22.72 73,22.57 R54.1
USBA_CONN2_I_ADJ: length 1.9
  TOP w0.1: U16.2 v2(51.73,28.67) R58.1
USBC_SEL: length 34.2
  TOP w0.1: v3(10.12,45.98) 10.63,45.47 12.32,45.47 14.7,43.09 14.7,41.61 15.24,41.07 15.24,38.89 15.61,38.52 15.61,38.18 15.24,37.81 15.24,35.9 16.11,35.03 16.11,24.86 12.32,21.07 12.32,19.46 12.37,19.41 R68.1 12.37,18.33 12.42,18.29 U6.9
  BOTTOM w0.1: v3(10.12,45.98) 10.14,45.98 10.58,45.54 J3.18
USBC_USB2_0_DN: length 6.3
  TOP w0.112: v1(42.05,10.99) 41.85,10.79 J7.A7
  L3 w0.117: J7.B7 40.92,9.21 40.92,10.99 41.28,11.35 41.69,11.35 v1(42.05,10.99)
  BOTTOM w0.112: v1(42.05,10.99) 41.95,11.08 42.44,11.57 42.44,11.8 42.56,11.92 42.56,12.28 U4.B2
USBC_USB2_0_DP: length 6.2
  TOP w0.112: v1(41.45,10.94) 41.46,10.94 41.35,10.83 41.35,10.14 J7.A6
  L3 w0.117: J7.B6 42.24,9.17 42.24,9.71 42.12,9.83 41.88,9.83 41.68,9.63 41.29,9.63 41.17,9.75 41.17,10.76 41.36,10.95 41.47,10.95 41.47,10.94 v1(41.45,10.94)
  BOTTOM w0.112: U4.A2 42.29,12.35 42.29,12.03 42.17,11.91 42.17,11.68 41.47,10.98 41.47,10.94 v1(41.45,10.94)
USBC_USB3_0_MUX1_RX_DN: length 5.7
  TOP w0.112: J7.B10 40,7.31 39.33,6.64 35.86,6.64 35.75,6.53 L7.2
USBC_USB3_0_MUX1_RX_DP: length 5.6
  TOP w0.112: J7.B11 39.2,7.88 39.31,7.77 39.57,7.77 39.73,7.61 39.73,7.42 39.22,6.92 35.86,6.92 35.75,7.04 L7.1
USBC_USB3_0_MUX1_TX_DN: length 5.7
  TOP w0.112: J7.A3 39.85,11.52 39.81,11.56 39.81,11.84 v1(39.75,11.84)
  BOTTOM w0.112: v1(39.75,11.84) 39.01,12.58 36.6,12.58 36.28,12.27 36.28,12.22
USBC_USB3_0_MUX1_TX_DP: length 5.7
  TOP w0.112: J7.A2 v1(39.35,11.39)
  BOTTOM w0.112: L6.1 36.88,12.31 38.24,12.31 38.36,12.19 38.36,11.66 38.44,11.58 38.58,11.58 38.66,11.66 38.66,12.25 38.72,12.31 38.89,12.31 39.34,11.86 39.34,11.67 39.35,11.66 v1(39.35,11.39)
USBC_USB3_0_MUX2_RX_DN: length 6.7
  TOP w0.112: J7.A10 43.44,10.23 43.44,10.84 43.61,11 43.61,11.21 44.12,11.71 46.26,11.71 47.26,10.71 47.41,10.71 47.52,10.61 48.04,10.61 48.3,10.36 48.3,10.32
USBC_USB3_0_MUX2_RX_DP: length 6.7
  TOP w0.112: L9.1 47.77,10.34 47.41,10.34 47.3,10.44 47.14,10.44 46.16,11.42 46,11.42 45.86,11.29 45.86,10.82 45.75,10.71 45.59,10.71 45.48,10.82 45.48,11.33 45.37,11.44 44.23,11.44 43.88,11.09 43.88,10.89 43.76,10.77 43.76,10.23 J7.A11
USBC_USB3_0_MUX2_TX_DN: length 1.3
  BOTTOM w0.112: J7.B3 43.45,7.98 43.45,7.17 L8.2
USBC_USB3_0_MUX2_TX_DP: length 1.3
  BOTTOM w0.112: J7.B2 43.73,7.95 43.73,7.19 L8.1
VCONN_DCDC_EN: length 19.7
  TOP w0.1: v1(42.9,20.23) 44.31,21.64 46.42,21.64 48.6,23.82 48.6,31.73 TP25.1 48.07,32.07 47.7,31.7 U17.4
  BOTTOM w0.1: J2.97 42.08,21.06 42.9,20.24 v1(42.9,20.23)
VCONN_I_ADJ: length 1.9
  TOP w0.1: U17.2 v2(47.05,28.67) 47.05,28.66 R55.1
VCONN_OCFLAG_TP: length 2.1
  TOP w0.1: TP33.1 48.15,27.68 48.15,28.85 47.7,29.3 U17.3
VDC_IN_CONN:
  vias: v2(67.47,41.63)
VDC_IN_FET:
  vias: v1(71.95,35.8) v1(72.19,33.98) v1(72.45,35.8) v1(72.69,33.98) v1(72.95,35.8) v1(73.19,33.98) v1(73.45,35.8) v1(73.86,33.99)
VDC_IN_R:
  vias: v1(65.7,51.13) v1(65.95,51.57) v1(65.96,50.69) v1(66.2,51.13) v1(66.21,50.25) v1(66.45,51.57) v1(66.47,50.68) v1(66.7,51.12) v1(66.73,50.25) v1(66.95,51.56) v1(66.99,50.67) v1(67.21,51.12) v1(67.23,50.23) v1(67.35,52.9) v1(67.33,52.4) v1(67.46,51.56) v1(67.5,50.67) v1(67.71,52.01) v1(67.71,51.12) v1(68,50.71) v1(68.32,51.56) v1(72.64,40.86) v1(72.86,41.31) v1(73.14,40.86) v1(73.23,41.8) v1(73.36,41.31) v1(73.64,40.86) v1(73.73,41.8) v1(73.86,41.31) v1(74.14,40.86)
VSYS_REG_BOOT: length 4.5
  BOTTOM w0.35: 65.64,48.28 64.91,48.28 63.51,49.68 v2(63.13,49.68) 62.1,49.68 C87.1
VSYS_REG_COMP: length 3.2
  BOTTOM w0.3: C90.1 C89.1 59.04,45.74 60.41,45.74 60.71,45.45 v3(60.71,45.11)
VSYS_REG_EN: length 4
  BOTTOM w0.1: v2(67.57,43.42) 67.57,44.73 67.42,44.88 67.29,44.88 R26.1
  BOTTOM w0.3: 65.64,45.74 66.75,45.74 66.88,45.62 67.15,45.62 R26.1
VSYS_REG_OUT:
  vias: v2(59.32,42.23)
VSYS_REG_PH: length 1.4
  BOTTOM w0.2: 60.24,48.28 61.05,49.09 C87.2
  vias: v2(47.55,48.1)
VSYS_REG_SENSE: length 2.8
  BOTTOM w0.3: R24.2 R31.1 59.31,43.93 59.49,43.75 v3(59.54,43.75) 59.54,44.17 59.84,44.48 U18.5
VSYS_REG_SS: length 2.2
  BOTTOM w0.2: v3(64.6,45.11) 64.6,44.83 64.95,44.48 U18.4
  BOTTOM w0.3: U18.4 65.64,44.47 C88.1

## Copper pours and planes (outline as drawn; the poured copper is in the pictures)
+5VP0V_HDMI_CONN on TOP: 21.4,10.42 21.4,7.72 21.26,7.58 20.6,7.58 20.38,7.8 20.38,8.24 20.56,8.42 21,8.42 21.1,8.52 21.1,10.42
+5VP0V_HDMI_CONN on BOTTOM: 21.12,6.26 21.12,7.53 21.41,7.82 21.41,9.09 21.33,9.17 21.07,9.17 20.43,8.53 20.43,6.62 20.79,6.26
+5VP0V_HDMI_OUT_FILT on BOTTOM: 23.55,5.42 23.55,6.94 21.16,6.94 21.16,5.42
+V1P1V on TOP: 61.78,35.39 61.78,36.81 61.75,36.81 61.78,36.84 61.78,37.74 64.88,37.74 64.95,37.67 64.95,36.66 64.59,36.66 64.58,36.65 63.57,36.65 63.57,35.64 63.32,35.39
+V1P1V_USB_HUB on TOP: 62.95,32.22 62.83,32.34 62.83,33.31 62.81,33.33 62.81,33.79 63.29,34.27 64.08,34.27 64.08,36.34 64.69,36.34 64.78,36.25 64.78,34.22 63.22,32.66 63.22,32.28 63.16,32.22
+V1P1V_USB_HUB on L5: 55.78,26.15 55.5,26.43 55.5,30.52 57.21,32.23 62.59,32.23 62.79,32.43 62.79,32.59 62.8,32.6 62.8,33.79 63.15,34.14 64.51,34.14 65.19,33.46 65.19,31.05 64.7,30.56 58.45,30.56 56.71,28.82 56.71,26.15
+V3P3V on TOP: 51.68,37.36 52.09,37.36 52.3,37.15 52.93,37.15 52.67,36.89 54.85,36.89 54.85,35.87 53.76,34.78 53.76,33.99 53.7,33.93 53.16,33.93 53.06,34.03 53.06,35.06 52.71,35.41 51.26,35.41 51.21,35.46 51.21,36.62 51.68,37.09
+V3P3V on L5: 32.67,15.21 32.61,15.27 32.61,16.03 32.76,16.18 33.81,16.18 36.04,18.41 44.62,18.41 44.63,18.4 45.08,18.4 50.02,23.34 50.02,32.56 52.83,35.37 52.83,35.63 52.96,35.76 54.37,35.76 54.51,35.62 54.51,34.22 52.3,32.01 52.3,21.47 47.54,16.71 39.65,16.71 39.65,16.67 38.19,15.21
+V3P3V_SW on TOP: 51.71,38.36 54.85,38.36 54.85,37.32 53.08,37.32 52.29,38.11 51.71,38.11
+V3P3V_USB_HUB on TOP: 54.26,34.66 54.26,33.93 54.58,33.61 56.47,33.61 56.68,33.4 56.68,32.4 56.85,32.23 57.06,32.23 57.22,32.39 57.22,34.29 56.85,34.66
+V3P3V_USB_HUB on L5: 55.85,24.85 55.85,25.17 55.48,25.54 55.15,25.54 54.58,26.11 54.58,27.59 54.25,27.92 54.25,30.69 54.67,31.11 54.67,33.15 56.02,34.5 61.09,34.5 61.37,34.22 62.54,34.22 62.79,33.97 62.79,32.43 62.59,32.23 62.33,32.23 62.27,32.29 57.13,32.29 55.54,30.7 55.54,26.25 56.58,25.21 56.58,24.85
+V5P0V on TOP: 63.09,14.37 62.03,15.43 62.03,16.72 62.18,16.87 62.18,21.41 63.55,22.78 64.68,22.78 68.35,26.45 68.35,33.21 66.18,35.38 66.18,37.88 64.83,39.23 62.4,39.23 62.16,38.99 61.78,38.99 61.78,41.35 61.7,41.43 59.13,41.43 58.76,41.06 54.5,41.06 52.37,38.93 52.37,38.92 52.05,38.6 51.68,38.6 51.67,38.61 51.67,41.03 49.65,41.03 47.55,38.93 47.55,36.67 51.23,32.99 51.23,31.36 49.63,31.36 49.63,33.08 46.55,33.08 46.55,31.36 45.87,31.36 45.43,31.8 45.43,33.42 45.36,33.49 44.85,33.49 44.52,33.82 43.05,33.82 42.53,33.3 42.53,31.36 42.23,31.36 41.48,32.11 41.48,38.07 45.54,42.13 46.28,42.13 50.12,45.97 59.88,45.97 59.88,45.96 61.7,44.14 63.63,44.14 64.61,43.16 64.61,42.8 67.74,39.67 68.1,39.67 70.78,36.99 70.78,33.33 71.53,32.58 71.53,28.24 72.21,27.56 72.21,27.24 72.22,27.25 72.22,25.56 72.02,25.36 71.72,25.36 69.87,23.51 69.87,16.28 67.96,14.37
+V5P0V on BOTTOM: 64.24,12.82 62.43,14.63 60.2,14.63 58.41,16.42 54.91,16.42 54.91,18.05 61.41,18.05 61.41,17.16 61.94,16.63 64.49,16.63 64.49,17.32 65.85,17.32 65.85,12.94 65.73,12.82
+V5P0V on BOTTOM: 22.17,0.76 15.49,7.44 6.6,7.44 6.6,8.35 9.22,8.35 9.24,8.33 16.5,8.33 17.53,7.3 18.74,7.3 20.44,5.6 20.44,5.24 21.05,4.63 21.41,4.63 22.11,3.93 23.55,3.93 23.55,3.96 23.58,3.93 23.55,3.93 23.55,2.21 23.66,2.1 54.41,2.1 63.8,11.49 63.8,13.62 65.82,13.62 65.85,13.59 65.85,8.36 58.25,0.76
+V5P0V on L2, L3, L4, L5: 64.93,15.93 64.93,16.2 64.51,16.62 62.47,16.62 61.91,16.06 61.91,15.55 63.1,14.36 64.52,14.36 64.94,14.78 64.94,15.92
+V5P0V_BREAKOUT on TOP: 45.44,48.83 45.44,43.94 46.56,43.94 46.56,48.83
+V5P0V_USBA_1 on TOP: 70.4,20.96 70.4,17.3 72.31,17.3 72.31,20.96
+V5P0V_USBA_2 on TOP: 51.26,17.35 50.11,18.5 50.11,21.75 48.75,23.11 48.75,29.86 51.29,29.86 51.29,28.31 52.01,27.59 52.01,17.35
+V5P0V_VCONN on TOP: 45.08,28.45 44.93,28.6 44.93,29.67 45.12,29.86 46.71,29.86 46.71,28.88 46.28,28.45
+VBUS on TOP: 43.22,22.21 43.07,22.36 43.07,22.69 43.42,23.04 43.42,25.81 41.14,28.09 41.14,28.45 40.91,28.45 40.76,28.61 40.76,29.68 40.95,29.86 42.54,29.86 42.54,28.49 45.03,26 45.03,23.09 44.15,22.21
+VBUS on BOTTOM: 43.62,15.92 43.25,16.29 43.25,21.5 42.36,22.39 42.36,23.72 42.37,23.71 43.46,23.71 44.42,22.75 44.42,20.63 44.66,20.39 44.66,15.99 44.59,15.92
+VBUS_USBC on BOTTOM: 40.26,8.6 40.06,8.8 40.06,9.83 40.92,10.69 42.26,10.69 43.6,12.03 44.11,12.03 44.25,11.89 44.25,9.91 42.94,8.6
+VBUS_USBC_F on BOTTOM: 43.41,15.6 43.41,12.6 43.59,12.42 44.01,12.42 44.1,12.51 44.1,15.6
GND on TOP: 66.69,17.16 68.73,17.16 68.82,17.25 68.82,17.63 68.47,17.98 66.36,17.98 66.29,17.91 66.29,17.56
GND on TOP: 0.25,0.25 0.25,53.75 84.75,53.75 84.75,0.25 ; 6 cut-outs
GND on BOTTOM: 0.25,0.25 0.25,53.75 84.75,53.75 84.75,0.25 ; 6 cut-outs
GND on L2, L4, L5: 0.25,0.25 0.25,53.75 84.75,53.75 84.75,0.25
GND on L3: 0.25,0.25 0.25,53.75 84.75,53.75 84.75,0.25 ; 5 cut-outs
VBATTERY on BOTTOM: 40.77,26.63 40.77,26.8 40.27,27.3 40.27,27.56 40.46,27.75 40.73,27.75 41.15,27.33 41.69,27.33 41.76,27.26 41.76,27 41.71,26.95 41.29,26.95 40.98,26.64 40.98,25.94 40.78,25.94 40.78,26.63
VBUS_USBA_1 on TOP: 70.4,12.91 70.4,16.92 71.3,16.92 71.3,12.91
VBUS_USBA_2 on TOP: 51,12.45 51,16.92 51.97,16.92 51.97,12.45
5P0V_PH on BOTTOM: 54.91,20.99 54.91,22.77 57.53,22.77 57.53,28.53 61.41,28.53 61.41,22.62 65.71,22.62 65.71,20.99
+1P1V_SW on TOP: 61.78,38.74 62.26,38.74 62.65,39.13 64.95,39.13 64.95,38.11 63.17,38.11 62.8,38.48 61.78,38.48
+1P8V_BREAKOUT on TOP: 43.44,45.4 43.44,48.83 44.51,48.83 44.51,46.13 43.8,45.42 43.8,45.4
+SYS_DCIN on TOP, L2, L3: 47.34,53.34 47.34,50.82 43.26,50.82 42.66,51.42 42.66,53.34
+SYS_DCIN on TOP, L2, L3: 49.29,52.58 49.29,51.62 50.56,51.62 50.56,52.58
+SYS_DCIN on TOP, L2, L3: 62.69,50.72 62.69,51.75 61.25,53.19 61,53.19 60.78,52.97 60.78,52.17 60.65,52.04 59.56,52.04 59.44,51.92 59.44,51.43 60.79,50.08 62.05,50.08
+SYS_DCIN on BOTTOM: 47.83,49.75 49.35,49.75 50.52,50.92 50.52,52.91 50.48,52.95 49.93,52.95 49.39,52.41 47.9,52.41 46.85,53.46 42.98,53.46 42.66,53.14 42.66,51.51 42.97,51.2 43.1,51.2 43.64,51.74 46.25,51.74 47.83,50.16
+SYS_DCIN on BOTTOM: 60.65,50.21 59.43,51.43 59.43,53.13 62.51,53.13 62.51,50.21
+SYS_DCIN on L4: 48.17,49.63 46.6,51.2 42.97,51.2 42.67,51.5 42.67,53.31 42.76,53.4 47.03,53.4 47.31,53.12 62.51,53.12 62.51,50.09 62.32,50.09 61.87,49.64 60.8,49.64 60.79,49.63 59.69,49.63 58.87,50.45 57.37,50.45 56.55,49.63
+SYS_DCIN on L5: 48.36,49.63 46.25,51.74 43.64,51.74 43.1,51.2 42.97,51.2 42.67,51.5 42.67,53.31 42.76,53.4 47.03,53.4 47.31,53.12 62.51,53.12 62.51,50.09 62.32,50.09 61.87,49.64 60.8,49.64 60.79,49.63
+VDC_IN on TOP: 72.25,28.14 71.84,28.55 71.84,32.53 75.52,32.53 75.52,31.51 75.11,31.1 75.11,30.6 74.19,29.68 74.19,28.23 74.1,28.14
+VDC_IN on BOTTOM: 69.12,19.7 69.12,21.03 71.22,21.03 71.22,22.23 69.12,22.23 69.12,27.06 66.79,29.39 66.79,35.6 64.42,37.97 64.42,43.59 66.18,43.59 66.18,42.86 67.5,42.86 67.5,46.12 64.74,46.12 64.74,47.9 68.72,47.9 69.92,46.7 69.92,44.69 70.51,44.1 70.51,41.12 71.09,40.54 71.09,33.21 74.62,33.21 74.87,32.96 74.87,31.42 74.98,31.31 74.98,30.89 74.76,30.67 74.76,30.24 73.71,29.19 73.7,29.19 73.7,19.7
+VDC_IN on L2, L3: 74.94,31.36 72.63,31.36 71.85,30.58 71.85,28.56 72.23,28.18 73.28,28.18 73.73,28.63 73.73,29.22 75.11,30.6 75.11,31.19
+VDC_IN on L4: 74.94,31.36 72.63,31.36 71.85,30.58 71.85,28.56 72.23,28.18 73.27,28.18 73.73,28.64 73.73,29.22 75.11,30.6 75.11,31.19
+VDC_IN on L5: 72.23,28.18 71.85,28.56 71.85,30.58 72.63,31.36 74.77,31.36 75.11,31.02 75.11,30.73 75.02,30.73 74.5,30.21 74.5,29.98 73.73,29.21 73.73,28.64 73.27,28.18
+VSYS on TOP: 18.96,22.17 20.64,22.17 20.83,21.98 20.83,21.71 20.29,21.17 19.43,21.17 18.81,21.79 18.81,22.02
+VSYS on TOP, L2, L3, L4: 19.16,29.75 19.16,26.96 19.52,26.96 19.52,29.75
+VSYS on TOP, L2, L3, L4: 50.5,41.39 49.1,41.39 47.92,40.21 47.92,39.84 48.22,39.54 48.83,39.54 48.92,39.63 48.92,40.09 49.69,40.86 50.18,40.86 50.53,41.21 50.53,41.36
+VSYS on BOTTOM: 55.31,41.79 55.31,39.25 47.81,39.25 47.81,41.79
+VSYS on BOTTOM: 20.95,26.07 20.95,22.89 22.68,22.89 22.68,26.07
+VSYS on BOTTOM: 6.77,40.24 6.47,40.54 6.47,40.55 5.92,41.1 5.92,47.33 6.84,48.25 13.79,48.25 13.88,48.16 13.88,44.93 13.28,44.93 13.28,45.63 13.02,45.89 13.02,46.55 12.91,46.66 12.13,46.66 11.49,46.02 11.49,44.93 10.88,44.93 10.88,45.63 10.53,45.97 10.53,45.97 9.75,46.75 7.39,46.75 7.13,46.49 7.13,44.13 7.88,43.38 7.88,40.88 8.26,40.88 8.26,40.53 7.97,40.24
+VSYS on BOTTOM: 19.26,21.14 18.81,21.59 18.81,22.95 23.57,22.95 23.57,23.56 24.18,23.56 24.18,22.87 24.17,22.86 24.17,21.97 24.33,21.81 24.53,21.81 25.58,22.86 25.58,23.55 25.57,23.56 26.18,23.56 26.18,21.25 26.07,21.14 22.35,21.14 22.07,21.42 20.54,21.42 20.26,21.14
+VSYS on BOTTOM: 19.12,25.94 19,26.06 19,29.63 19.23,29.86 24.77,29.86 25.44,29.19 25.44,27.1 24.98,26.64 24.98,25.94 24.78,25.94 24.78,28.38 22.98,28.39 22.98,25.94
+VSYS on L2, L3, L4: 18.96,22.17 20.64,22.17 20.72,22.09 20.72,21.6 20.29,21.17 19.57,21.17 18.81,21.93 18.81,22.02
+VSYS on L5: 19.08,21.33 14.2,26.21 7.46,26.21 5.64,28.03 5.64,42.32 7.31,43.99 8.71,43.99 8.9,44.18 8.9,45.61 9.96,46.67 13.27,46.67 13.9,46.04 13.9,43.64 13.24,42.98 10.41,42.98 9.13,41.7 9.13,37.8 10.28,36.65 16.25,36.65 17.05,37.45 39.66,37.45 44,41.79 50.87,41.79 52.46,40.2 52.46,38.79 48.76,35.09 47.97,35.09 40.83,27.95 40.02,27.95 38.95,29.02 38.95,30.04 36.78,32.21 26.04,32.21 22.72,28.89 22.72,23.71 20.34,21.33
RF_ANT_WIFI_A on BOTTOM (solid shape): 84.75,41.57 76.09,41.57 76.09,41.77 84.55,41.77 84.55,53.75 84.75,53.75
RF_ANT_WIFI_B_BT on BOTTOM (solid shape): 84.75,18.25 83.89,18.25 83.15,20.45 81.03,21.4 78.89,20.49 78.11,18.3 76.09,18.3 76.09,18.5 77.9,18.5 78.82,20.7 81.03,21.6 83.22,20.67 84.1,18.45 84.55,18.45 84.55,29 84.75,29
VDC_IN_CONN on TOP: 68.01,40.04 64.93,43.12 64.93,44.16 65.84,45.07 70.01,45.07 71.9,43.18 71.9,41.17 70.77,40.04
VDC_IN_FET on TOP: 71.18,33.33 71.18,36.29 71.75,36.86 73.62,36.86 73.62,35.35 73.9,35.35 73.9,33.33
VDC_IN_FET on BOTTOM, L3, L4, L5: 71.82,33.85 71.82,35.93 73.9,35.93 73.9,33.85
VDC_IN_FET on L2: 71.18,33.73 71.18,36.3 71.74,36.86 73.64,36.86 73.64,35.44 74.11,34.97 74.11,33.73
VDC_IN_R on TOP: 71.88,37.38 71.88,40.71 72.4,41.23 72.4,44.23 70.8,45.83 65.84,45.83 65.84,46.13 64.28,46.13 64.28,47.05 65.45,47.05 65.45,48.15 66.99,48.15 66.99,48.19 67.45,48.19 67.45,49.98 65.45,49.98 65.45,51.24 67.36,53.15 73.06,53.15 74.31,51.9 74.31,37.38
VDC_IN_R on BOTTOM: 64.85,49.58 64.31,50.12 64.31,53.15 67.46,53.15 68.65,51.96 68.65,49.58
VDC_IN_R on BOTTOM, L3, L4, L5: 72.53,40.61 74.21,40.61 74.28,40.68 74.28,41.61 73.84,42.05 73.12,42.05 72.39,41.32 72.39,40.75
VDC_IN_R on L2: 72.42,40.59 72.42,42.77 72.2,42.99 72.2,44.54 70.91,45.83 65.45,45.83 65.45,52.91 65.69,53.15 73.06,53.15 74.31,51.9 74.31,40.59
VDC_IN_R on L3, L4, L5: 66.1,49.99 67.64,49.99 68.58,50.93 68.58,52.03 67.45,53.16 67.26,53.16 67.08,52.98 67.08,51.95 66.95,51.82 65.84,51.82 65.45,51.43 65.45,50.64
VSYS_REG_OUT on BOTTOM: 57.09,38.09 57.09,41.79 56.13,42.75 50.43,42.75 50.43,44.53 56.93,44.53 58.08,43.38 58.69,43.38 58.89,43.58 60.74,43.58 60.83,43.49 60.83,40.75 58.17,38.09
VSYS_REG_PH on BOTTOM: 43.58,47.64 43.58,51.45 43.59,51.46 46.19,51.46 46.19,49.43 46.39,49.43 46.67,49.15 48.13,49.15 48.4,49.42 48.9,49.42 48.89,49.43 61.24,49.43 61.24,49.09 60.71,49.09 60.71,48.64 61.24,48.64 61.24,47.64

Small or netless copper shapes (teardrops, artwork), in the pictures only: 17 on TOP, 7 on BOTTOM

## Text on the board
Ref Des/Assembly Bottom: ASSEMBLY BOTTOM
Board Geometry/Soldermask Bottom: 1 | +5V | FAN HEADER | GND | 100 | DEBUG | UART | VSYS | SENSE | J1 | RTS | TXD | RXD | CTS | WIFI A | WIFI B | J41749-001
User.Comments: UNLESS OTHERWISE SPECIFIED: | 1. DIMENSIONS ARE IN MILLIMETERS | 2. BREAK ALL SHARP EDGES | 3. DO NOT SCALE DRAWING | 4. TOLERANCES | ANGLES +/- | xx +/- | xxx +/- | DRN BY | CHK BY | ENGR | APVD | SIGNATURE | DATE | TITLE | SIZE | mIZE | SCALE | DCLC | CLASS CODE | DOCUMENT NUMBER | 3065 BOWERS AVE | CALIF.  95051 | INTEL CONFIDENTIAL | SANTA CALRA | SHEET      OF | REV
Ref Des/Assembly Top: ASSEMBLY TOP
Board Geometry/Soldermask Top: J12 | 2 | 1 | J13 | 60 | 59 | 39 | 40 | DNX BOOT | PWR | 3 | 0 | 8-24V | IN | IN FINLAND | DESIGNED | MICRO SD CARD | RTC BATTERY | HDMI | USB-C | USB3.0 HOST 2 | R1 | USB3.0 HOST 1
XSECTION_CHART: *  SURFACE - AIR 0 MM | L1: TOP CONDUCTOR - COPPER 0.03 MM | *  DIELECTRIC - FR-4 0.062 MM | L2: L2 PLANE - COPPER 0.03 MM | *  DIELECTRIC - FR-4 0.133 MM | L3: L3 CONDUCTOR - COPPER 0.03 MM | *  DIELECTRIC - FR-4 0.935 MM | L4: L4 PLANE - COPPER 0.03 MM | L5: L5 CONDUCTOR - COPPER 0.03 MM | L6: BOTTOM CONDUCTOR - COPPER 0.03 MM | DESIGN CROSS SECTION CHART | ___________________________ | TOTAL THICKNESS 1.505 MM | 1-6 | 5-6 | xxxxxx-xxx
PAGE_OUTLINE: THIS DRAWING CONTAINS INFORMATION | WHICH IS THE PROPRIETARY PROPERTY | OF INTEL CORPORATION. THIS DRAWING | IS RECEIVED IN CONFIDENCE AND ITS | CONTENTS MAY NOT BE DISCLOSED WITH- | OUT THE PRIOR WRITTEN CONSENT OF | INTEL CORPORATION. | D | C | B | A | 8 | 7 | 6 | 5 | 4 | 3 | 2 | 1
DIMENSION: AREA | ANTENNA
DISPLAY_TOP: 2D-ID | LABEL TARGET
User.12: VIACAP SECONDARY | 1 | * | AM,PB,VC,                  ,S | xxxxxx | 01
User.13: SOLDER MASK (SECONDARY) | 1 | - | AM,PB,SM,GT96B | xxxxxx | 02
User.14: LEGEND (SECONDARY) | 1 | * | AM,PB,SS,GT96B | xxxxxx | 01
User.15: SOLDER PASTE (SECONDARY) | 1 | * | AM,PBA,SP,GT96B            ,S | xxxxxx | 02
User.16: SOLDER MASK (PRIMARY) | 1 | - | AM,PB,SM,GT96B | xxxxxx | 01
User.17: LEGEND (PRIMARY) | 1 | * | AM,PB,SS,GT96B | xxxxxx | 01
User.18: REV | 01 | INITIAL RELEASE | DESCRIPTION | DFT | REVISIONS | 10/18/16 | DATE | CHK | APVD | MIG Design Team | 1:1 | 1 | D | PB,MP,FAB DWG, GT96B, FAB 4 | 8. OUTRIGGER (WASTE) MATERIAL TO CONTAIN FULL METALIZATION WITH THE EXCEPTION | 9  THESE KIND OF AREAS TO BE FREE OF METALIZATION. | 10  FIDUCIAL TARGETS PER DETAIL "A" ON BOTH PRIMARY AND SECONDARY SIDES AS INDICATED. | 11  ADD 3.05MM +0.05 / -0.05 NON-PLATED TOOLING HOLES x4 | 12  MARK IMAGE #(1, 2, 3, 4) ON OUTRIGGER TOP & BOTTOM SOLDERMASK APPROXIMATELY WHERE SHOWN. | 7. TYPICAL ROUTE SLOTS 2.49. | 6  MARK "MP" IDENTIFICATION NUMBER, AND LETTERS APPROXIMATELY | 3  THE CENTER OF THESE HOLES ESTABLISH DATUM -A-. | 4  DATUM -B- IS PERPENDICULAR TO DATUM -A- THROUGH THE CENTER OF THIS HOLE. | 5  THIS DOCUMENT ALSO EXISTS ON ELECTRONIC MEDIA. | 1. ITEM IDENTIFICATION NUMBER IS PARENT LINE ITEM NUMBER ON | NOTES:  UNLESS OTHERWISE SPECIFIED: | 2. DIMENSIONING AND TOLERANCING PER ANSI Y14.5M. | WHERE SHOWN ON PRIMARY SIDE. | OF THE POST-ASSEMBLY 2.49MM ROUTE PATHS. | THE POST ASSEMBLY ROUTE PATHS CONSISTS OF THE 2.49MM PERIMETER SURROUNDING THE SINGLE IMAGES. | ENGINEERING BILL OF MATERIAL. | FIDUCIALS x5 | DETAIL A | 10 | 7 | Soldermask | opening | Copper/Metal | DETAIL B | ROUTER TABS | 11 | 4x | A | B | 12 | 9 | 2 | 4 | ******-*** | 8 | 6 | 3
User.19: REV | 01 | 02 | SML0402 adjustment and etch at L27 | INITIAL RELEASE | DESCRIPTION | DFT | REVISIONS | 10/18/2016 | 03/13/2017 | DATE | CHK | APVD | MIG Design Team | 10/18/16 | 1:1 | 1 | xxxxxx | 10 | 4 | A | 19 | FINISHED BOARD THICKNESS 1.55mm +/-10% | MAY BE MODIFIED TO MEET TARGET IMPEDANCE. | 7 | 90 OHM DIFF PAIRS - 0.112mm TRACE / 0.163m SPACE REF GND L2/L5 | 45 OHM SINGLE ENDED - 0.140mm REF GND L2/L5 | 50 OHM SINGLE ENDED - 0.430mm REF GND L4 | LINE WIDTH AND DIELECTRIC THICKNESS | LAYERS 5 | IMPEDANCE: | LAYERS 1 & 6 | 45 OHM SINGLE ENDED - 0.084mm | LAYERS 3 | 90 OHM DIFF PAIRS - 0.076 TRACE / 0.133m SPACE REF GND L4/L6 | 45 OHM SINGLE ENDED - 0.208mm | 90 OHM DIFF PAIRS - 0.117mm TRACE / 0.133mm SPACE | B | 5 | 14. VENDOR SHALL RECEIVE STACK-UP APPROVAL PRIOR TO FAB START. | 13. FINISHED BOARD MUST BE COMPLIANT WITH THE RESTRICTION ON USE OF | HAZARDOUS SUBSTANCES(ROHS)DIRECTIVE. TEST DATA MUST BE AVALIABLE | TO DEMONSTRATE THAT IT WILL BE ABLE TO RELIABLY HANDLE REPEATED | EXPOSURE TO ELEVATED TEMPERATURES REQUIRED ON LEAD FREE SOLDER PROCESS. | 11. PCB MATERIAL HALOGEN FREE (BR<900PPM,CL<900PPM) FR4 UL 94V-0, | Tg 150C,FLAME RETARDANT GLASS. | (ANY MATERIAL DEVIATION MUST BE APPROVED) | A. RoHS COMPLIANCE CERTIFICATE SHALL BE AVAILABLE UPON REQUEST | B. THE BOARD PACKAGE MUST BE IDENTIFIED AS RoHS COMPLIANT. PACKAGE OF | FINISHED PANELS MUST BE IDENTIFIED AS RoHS COMPLIANT. | 12. ALL SOLDERMASK TO BE HALOGEN FREE (BR<900 PPM, CL<900PPM) | A. NANYA NPG150 CORES AND PREPREG | B. HITACHI MCL-BE-67G(H) CORES AND PREPREG | C. ITEQ IT-140 GTC/BS CORES AND PREPREG | D. MATSUSHITA R1551V CORES AND PREPREG | E. PANASONIC R1566W (CORE) AND R1551W (PREPREG) | 8.  SURFACE FINISH: | 2. THIS DRAWING ALSO EXISTS ON ELECTRONIC MEDIA. | 3. FABRICATE PER INTEL SPECIFICATION A84501 | 1. PART NUMBER IS PARENT ITEM IDENTIFICATION | 5. DATUM -A- IS ESTABLISHED PERPENDICULAR TO | 4. THE CENTER OF THESE TWO HOLES ESTABLISH DATUM -B-. | 7  10% IMPEDANCE TOLERANCE IS REQUIRED FOR ALL CONFIGURATIONS UNLESS OTHERWISE SPECIFIED. | 6. DIMENSIONING AND TOLERANCING PER ANSI Y14.5M. | NOTES: UNLESS OTHERWISE SPECIFIED: | USE ORIGINAL SHAPE FOR SOLDERMASK OPENINGS | SOLDERMASK CLEARENCE FOR ALL OTHER PADS IS 50um | MINIMUM SOLDERMASK WEB IS 71um. | DO NOT USE IRREGULAR COMPENSATION FOR BGA PADS | SOLDERMASK CLEARENCE FOR ALL 0.4mm PITCH BGA PAD IS 37.5um | NUMBER ON ENGINEERING BILL OF MATERIAL. | DATUM -B- THROUGH THE CENTER OF THIS HOLE. | LATEST REVISION. | MAINTAIN TRACE WIDTH BY COMPENSATING SPACE ACCORDINGLY UP TO 5 MILS(SPEFIALLY INTO GROUND/SIGNAL PLANES) | ROUTED PCB EDGE TO SMT PAD EDGE 7 MILS +0MIL / -12MILS | SECONDARY SURFACE FINISH: ENIG PER INTEL PCB SPECIFICATION A84501. | PRIMARY SURFACE FINISH: ENIG PER INTEL PCB SPECIFICATION A84501. | PROCESS FLOW | D | PB,FAB DRAWING,GT96B, FAB A | LAYER STACKUP
User.21: SHEET | TITLE | SCALE 1:1 | LAYER | OF | DOCUMENT NUMBER | REV | MASTER | 10/18/16
User.22: 6 | PB,AM LAYERS,GT96B | xxxxxx | 02
User.23: LAYER 1 (PRIMARY SIDE) | 1
User.24: LAYER 2 (GROUND) | 2
User.25: LAYER 3 (SIGNAL AND GROUND) | 3
User.26: LAYER 6 (SECONDARY SIDE) | 6
User.27: PRIMARY PASTE (PRIMARY) | AM,PBA,SP,GT96B            ,P | xxxxxx | 01
User.28: LAYER 3 (SIG 1) | 3
User.29: LAYER 4 (GROUND) | 4
User.31: LAYER 5 (SIGNAL AND GROUND) | 5
User.41: FIGURE | SIZE | 0.25 | 0.4064 | 0.7112 | 2.5908 | 0.6604 | 0.762 | 0.8001 | 1.2 | 1.3 | 2.4892 | 1.397x0.508 | 1.4478x0.6096 | 1.6x0.8 | 1.6002x0.508 | 1.7018x0.6096 | 1.905x0.6096 | 0.9652x0.6604 | DRILL CHART: TOP to BOTTOM | ALL UNITS ARE IN MILLIMETERS | TOLERANCE | +0.0762/-0.0762 | +0.0508/-0.0508 | +0.03/-0.03 | +0.1/-0.0 | +0.0508/-0.0254 | +0.1016/-0.1016 | +0.0508/-0.0 | PLATED | NON-PLATED | QTY | 1553 | 12 | 18 | 4 | 1 | 2 | 3
User.44: FIGURE | SIZE | 0.1 | DRILL CHART: L5 to BOTTOM | ALL UNITS ARE IN MILLIMETERS | TOLERANCE | +0.05/-0.05 | PLATED | QTY | 23
